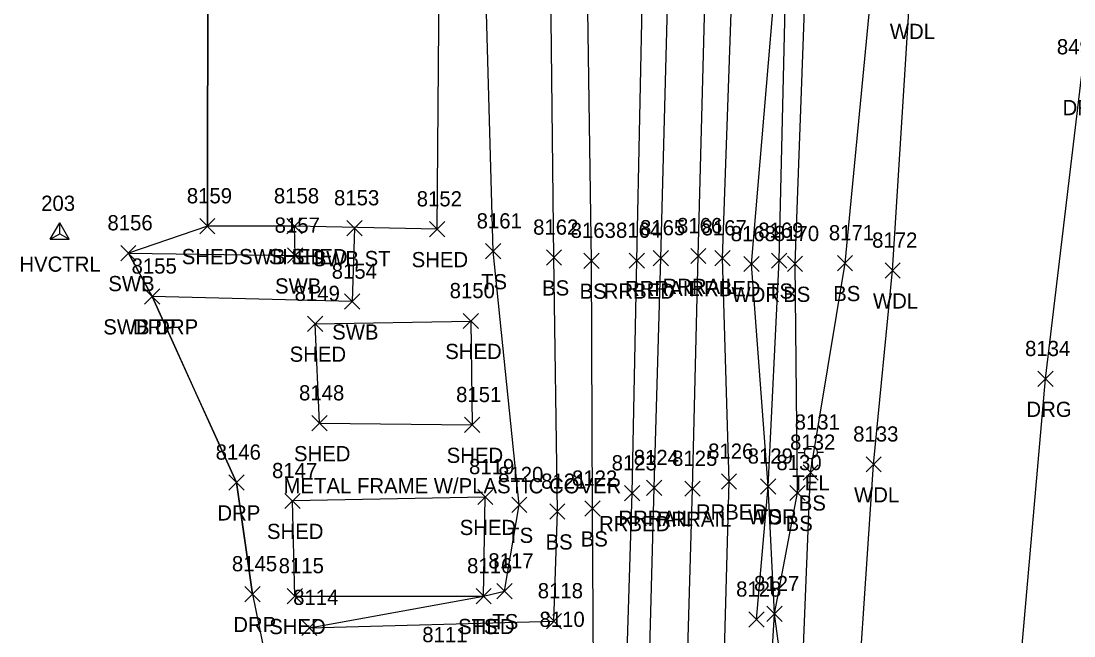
# Model space of a CAD drawing. Extents: x 1769141 to 1770911, y 735471 to 741449.
# Drawn here: x 1770186.3 to 1770324.8, y 736785 to 736865.8 of the extents above; entities that cross this region are included whole.
import ezdxf

# ---------------------------------------------------------------- set-up
doc = ezdxf.new("R2010")
doc.units = 0
for name, color, linetype in [('C_A', 7, 'Continuous'), ('C_I', 7, 'Continuous'), ('CPSM', 7, 'Continuous'), ('L_A', 7, 'Continuous'), ('L_C', 7, 'Continuous'), ('L_I', 7, 'Continuous'), ('L_TIC', 7, 'Continuous'), ('LAWA', 7, 'Continuous'), ('LBC', 7, 'Continuous'), ('LELB', 7, 'Continuous'), ('LSOGP', 7, 'Continuous'), ('R_A', 7, 'Continuous'), ('R_I', 7, 'Continuous'), ('R_TIC', 7, 'Continuous'), ('RDG', 7, 'Continuous'), ('RDP', 7, 'Continuous'), ('RR', 7, 'Continuous'), ('RRB', 7, 'Continuous'), ('RSW', 7, 'Continuous'), ('U_A', 7, 'Continuous'), ('U_I', 7, 'Continuous'), ('UP', 7, 'Continuous')]:
    doc.layers.add(name, color=color, linetype=linetype)

msp = doc.modelspace()

# ---------------------------------------------------------------- linework, layer by layer
at = {"layer": 'CPSM'}
for p, q in [((1770190.13, 736837.13), (1770191.38, 736839.3)), ((1770192.63, 736837.13), (1770191.38, 736839.3)), ((1770191.38, 736837.86), (1770191.38, 736839.3)), ((1770190.13, 736837.13), (1770191.38, 736837.86)), ((1770191.38, 736837.86), (1770191.38, 736837.86)), ((1770191.38, 736837.86), (1770192.63, 736837.13)), ((1770190.13, 736837.13), (1770192.63, 736837.13))]:
    msp.add_line(p, q, dxfattribs=at)
at = {"layer": 'L_TIC'}
for points in [[(1770209.8, 736837.85), (1770211.8, 736839.85)], [(1770211.8, 736837.85), (1770209.8, 736839.85)], [(1770221.25, 736837.85), (1770223.25, 736839.85)], [(1770223.25, 736837.85), (1770221.25, 736839.85)], [(1770240.03, 736837.45), (1770242.03, 736839.45)], [(1770242.03, 736837.45), (1770240.03, 736839.45)], [(1770240.03, 736837.45), (1770242.03, 736839.45)], [(1770242.03, 736837.45), (1770240.03, 736839.45)], [(1770247.39, 736834.55), (1770249.39, 736836.55)], [(1770249.39, 736834.55), (1770247.39, 736836.55)], [(1770255.39, 736833.73), (1770257.39, 736835.73)], [(1770257.39, 736833.73), (1770255.39, 736835.73)], [(1770260.32, 736833.3), (1770262.32, 736835.3)], [(1770262.32, 736833.3), (1770260.32, 736835.3)], [(1770281.38, 736832.87), (1770283.38, 736834.87)], [(1770283.38, 736832.87), (1770281.38, 736834.87)], [(1770285.01, 736833.32), (1770287.01, 736835.32)], [(1770287.01, 736833.32), (1770285.01, 736835.32)], [(1770287.1, 736832.89), (1770289.1, 736834.89)], [(1770289.1, 736832.89), (1770287.1, 736834.89)], [(1770293.68, 736832.99), (1770295.68, 736834.99)], [(1770295.68, 736832.99), (1770293.68, 736834.99)], [(1770299.94, 736832.02), (1770301.94, 736834.02)], [(1770301.94, 736832.02), (1770299.94, 736834.02)], [(1770223.98, 736825.02), (1770225.98, 736827.02)], [(1770225.98, 736825.02), (1770223.98, 736827.02)], [(1770244.45, 736825.38), (1770246.45, 736827.38)], [(1770246.45, 736825.38), (1770244.45, 736827.38)], [(1770224.55, 736811.94), (1770226.55, 736813.94)], [(1770226.55, 736811.94), (1770224.55, 736813.94)], [(1770224.55, 736811.94), (1770226.55, 736813.94)], [(1770226.55, 736811.94), (1770224.55, 736813.94)], [(1770244.64, 736811.72), (1770246.64, 736813.72)], [(1770246.64, 736811.72), (1770244.64, 736813.72)], [(1770244.64, 736811.72), (1770246.64, 736813.72)], [(1770246.64, 736811.72), (1770244.64, 736813.72)], [(1770297.44, 736806.53), (1770299.44, 736808.53)], [(1770299.44, 736806.53), (1770297.44, 736808.53)], [(1770289.15, 736805.45), (1770291.15, 736807.45)], [(1770291.15, 736805.45), (1770289.15, 736807.45)], [(1770289.15, 736805.45), (1770291.15, 736807.45)], [(1770291.15, 736805.45), (1770289.15, 736807.45)], [(1770283.57, 736803.63), (1770285.57, 736805.63)], [(1770285.57, 736803.63), (1770283.57, 736805.63)], [(1770283.57, 736803.63), (1770285.57, 736805.63)], [(1770285.57, 736803.63), (1770283.57, 736805.63)], [(1770246.36, 736802.24), (1770248.36, 736804.24)], [(1770248.36, 736802.24), (1770246.36, 736804.24)], [(1770287.42, 736802.77), (1770289.42, 736804.77)], [(1770289.42, 736802.77), (1770287.42, 736804.77)], [(1770221, 736801.72), (1770223, 736803.72)], [(1770223, 736801.72), (1770221, 736803.72)], [(1770221, 736801.72), (1770223, 736803.72)], [(1770223, 736801.72), (1770221, 736803.72)], [(1770250.83, 736801.2), (1770252.83, 736803.2)], [(1770252.83, 736801.2), (1770250.83, 736803.2)], [(1770260.47, 736800.73), (1770262.47, 736802.73)], [(1770262.47, 736800.73), (1770260.47, 736802.73)], [(1770255.84, 736800.33), (1770257.84, 736802.33)], [(1770257.84, 736800.33), (1770255.84, 736802.33)], [(1770248.88, 736789.85), (1770250.88, 736791.85)], [(1770250.88, 736789.85), (1770248.88, 736791.85)], [(1770221.31, 736789.21), (1770223.31, 736791.21)], [(1770223.31, 736789.21), (1770221.31, 736791.21)], [(1770221.31, 736789.21), (1770223.31, 736791.21)], [(1770223.31, 736789.21), (1770221.31, 736791.21)], [(1770246.14, 736789.21), (1770248.14, 736791.21)], [(1770248.14, 736789.21), (1770246.14, 736791.21)], [(1770246.14, 736789.21), (1770248.14, 736791.21)], [(1770248.14, 736789.21), (1770246.14, 736791.21)], [(1770284.4, 736786.87), (1770286.4, 736788.87)], [(1770286.4, 736786.87), (1770284.4, 736788.87)], [(1770284.4, 736786.87), (1770286.4, 736788.87)], [(1770286.4, 736786.87), (1770284.4, 736788.87)], [(1770255.39, 736785.92), (1770257.39, 736787.92)], [(1770257.39, 736785.92), (1770255.39, 736787.92)], [(1770282.04, 736786.14), (1770284.04, 736788.14)], [(1770284.04, 736786.14), (1770282.04, 736788.14)], [(1770223.22, 736785.05), (1770225.22, 736787.05)], [(1770225.22, 736785.05), (1770223.22, 736787.05)], [(1770223.22, 736785.05), (1770225.22, 736787.05)], [(1770225.22, 736785.05), (1770223.22, 736787.05)]]:
    msp.add_lwpolyline(points, dxfattribs=at)
at = {"layer": 'LAWA'}
for points in [[(1770295.56, 736765.07), (1770288.47, 736765.03), (1770285.4, 736787.87), (1770284.57, 736804.63), (1770282.38, 736833.87), (1770287.4, 736893.59), (1770286.58, 736936.63), (1770289.46, 736968.99), (1770291.49, 736986.73), (1770290, 737012.94), (1770290.58, 737048.83), (1770292.25, 737100.02), (1770294.09, 737129.48), (1770297.9, 737178.74), (1770298.45, 737224.98), (1770303.27, 737281.64), (1770303.62, 737324.77), (1770304.03, 737377.4)], [(1770295.56, 736765.07), (1770298.44, 736807.53), (1770300.94, 736833.02), (1770303.15, 736868.46), (1770304.73, 736899.95), (1770312.24, 736920.03), (1770307.96, 736948.77), (1770308.9, 736965.25), (1770306.38, 736996.36), (1770309.8, 737006.68), (1770311.39, 737048.91), (1770314.52, 737106.24), (1770314.64, 737122.83), (1770358.1, 737137.42)]]:
    msp.add_lwpolyline(points, dxfattribs=at)
at = {"layer": 'LBC'}
for points in [[(1770241.03, 736838.45), (1770222.25, 736838.85), (1770210.8, 736838.85), (1770210.86, 736875.84), (1770211.96, 736934.94), (1770241.81, 736934.81)], [(1770241.03, 736838.45), (1770241.81, 736934.81)], [(1770225.55, 736812.94), (1770224.98, 736826.02), (1770245.45, 736826.38), (1770245.64, 736812.72)], [(1770225.55, 736812.94), (1770245.64, 736812.72)], [(1770222.31, 736790.21), (1770247.14, 736790.21), (1770247.36, 736803.24), (1770222, 736802.72)], [(1770222.31, 736790.21), (1770222, 736802.72)]]:
    msp.add_lwpolyline(points, dxfattribs=at)
at = {"layer": 'LELB'}
for points in [[(1770224.22, 736786.05), (1770247.14, 736790.21), (1770249.88, 736790.85), (1770251.83, 736802.2), (1770248.39, 736835.55), (1770245.85, 736926.39), (1770250.04, 736949.23), (1770249.46, 736962.04), (1770235.3, 736982.59), (1770222.78, 736985.92)], [(1770278.54, 736722.58), (1770283.75, 736760.01), (1770285.4, 736787.87), (1770288.42, 736803.77), (1770288.1, 736833.89), (1770290.15, 736888.9), (1770292.54, 736921.49), (1770293.89, 736967.31), (1770294.41, 736976.29)], [(1770290.15, 736806.45), (1770294.68, 736833.99), (1770298.74, 736875.93), (1770299.66, 736922.72), (1770301.17, 736965.94), (1770297.99, 736975.93), (1770294.41, 736976.29)], [(1770224.22, 736786.05), (1770256.39, 736786.92), (1770256.84, 736801.33), (1770256.39, 736834.73), (1770255.46, 736917.15), (1770257.29, 736941.61)], [(1770261.5, 736721.42), (1770261.72, 736759.56), (1770261.47, 736801.73), (1770261.32, 736834.3), (1770260.25, 736909.24), (1770259.41, 736941.57), (1770257.29, 736941.61)], [(1770283.04, 736787.14), (1770284.57, 736804.63), (1770286.01, 736834.32), (1770287.4, 736893.59)], [(1770291.41, 736724.35), (1770288.47, 736765.03), (1770290.15, 736806.45)]]:
    msp.add_lwpolyline(points, dxfattribs=at)
at = {"layer": 'LSOGP'}
msp.add_lwpolyline([(1770222.78, 736985.92), (1770211.96, 736934.94), (1770210.86, 736875.84), (1770210.8, 736838.85), (1770200.41, 736835.3), (1770203.53, 736829.61), (1770206.3, 736823.49), (1770209.08, 736817.38), (1770211.86, 736811.26), (1770214.63, 736805.15), (1770215.68, 736797.81), (1770216.73, 736790.47), (1770221.43, 736767.51)], dxfattribs=at)
at = {"layer": 'R_TIC'}
for points in [[(1770221.25, 736837.85), (1770223.25, 736839.85)], [(1770223.25, 736837.85), (1770221.25, 736839.85)], [(1770229.16, 736837.59), (1770231.16, 736839.59)], [(1770231.16, 736837.59), (1770229.16, 736839.59)], [(1770199.41, 736834.3), (1770201.41, 736836.3)], [(1770201.41, 736834.3), (1770199.41, 736836.3)], [(1770221.34, 736833.99), (1770223.34, 736835.99)], [(1770223.34, 736833.99), (1770221.34, 736835.99)], [(1770266.29, 736833.32), (1770268.29, 736835.32)], [(1770268.29, 736833.32), (1770266.29, 736835.32)], [(1770269.45, 736833.65), (1770271.45, 736835.65)], [(1770271.45, 736833.65), (1770269.45, 736835.65)], [(1770274.38, 736833.93), (1770276.38, 736835.93)], [(1770276.38, 736833.93), (1770274.38, 736835.93)], [(1770277.55, 736833.64), (1770279.55, 736835.64)], [(1770279.55, 736833.64), (1770277.55, 736835.64)], [(1770202.53, 736828.61), (1770204.53, 736830.61)], [(1770204.53, 736828.61), (1770202.53, 736830.61)], [(1770202.53, 736828.61), (1770204.53, 736830.61)], [(1770204.53, 736828.61), (1770202.53, 736830.61)], [(1770228.85, 736827.94), (1770230.85, 736829.94)], [(1770230.85, 736827.94), (1770228.85, 736829.94)], [(1770320.05, 736817.77), (1770322.05, 736819.77)], [(1770322.05, 736817.77), (1770320.05, 736819.77)], [(1770320.05, 736817.77), (1770322.05, 736819.77)], [(1770322.05, 736817.77), (1770320.05, 736819.77)], [(1770213.63, 736804.15), (1770215.63, 736806.15)], [(1770215.63, 736804.15), (1770213.63, 736806.15)], [(1770278.42, 736804.27), (1770280.42, 736806.27)], [(1770280.42, 736804.27), (1770278.42, 736806.27)], [(1770265.68, 736802.74), (1770267.68, 736804.74)], [(1770267.68, 736802.74), (1770265.68, 736804.74)], [(1770268.57, 736803.44), (1770270.57, 736805.44)], [(1770270.57, 736803.44), (1770268.57, 736805.44)], [(1770273.62, 736803.33), (1770275.62, 736805.33)], [(1770275.62, 736803.33), (1770273.62, 736805.33)], [(1770215.73, 736789.47), (1770217.73, 736791.47)], [(1770217.73, 736789.47), (1770215.73, 736791.47)]]:
    msp.add_lwpolyline(points, dxfattribs=at)
at = {"layer": 'RDG'}
for points in [[(1770321.05, 736818.77), (1770325.8, 736858.44), (1770334.35, 736894.2), (1770350.3, 736909.29), (1770357.01, 736936.47)], [(1770306.26, 736740.41), (1770316.78, 736770.28), (1770321.05, 736818.77)]]:
    msp.add_lwpolyline(points, dxfattribs=at)
at = {"layer": 'RDP'}
msp.add_lwpolyline([(1770216.73, 736790.47), (1770214.63, 736805.15), (1770203.53, 736829.61)], dxfattribs=at)
at = {"layer": 'RR'}
for points in [[(1770267.4, 736722.31), (1770268.34, 736758.82), (1770269.57, 736804.44), (1770270.45, 736834.65), (1770272.42, 736909.27), (1770273.15, 736938.32), (1770274.05, 736970.76), (1770275.07, 737005.76), (1770276.22, 737052.19), (1770277.52, 737098.47), (1770278.47, 737131.31), (1770279.73, 737178.68), (1770281, 737226.57), (1770282.34, 737274.07)], [(1770272.41, 736722.1), (1770273.29, 736759.01), (1770274.62, 736804.33), (1770275.38, 736834.93), (1770277.26, 736906.22), (1770278.11, 736938.08), (1770278.9, 736969.65), (1770279.86, 737006.36), (1770281.15, 737052.02), (1770282.49, 737099.38), (1770283.42, 737130.8), (1770284.55, 737178.73), (1770285.97, 737226.12), (1770287.25, 737273.96)]]:
    msp.add_lwpolyline(points, dxfattribs=at)
at = {"layer": 'RRB'}
for points in [[(1770264.61, 736722.25), (1770265.29, 736759.21), (1770266.68, 736803.74), (1770267.29, 736834.32), (1770268.85, 736909.78), (1770270.22, 736938.92), (1770271.46, 736972.05), (1770272.55, 737004.83), (1770273.67, 737052.68), (1770274.45, 737097.79), (1770275.89, 737131.57), (1770277.22, 737178.3), (1770278.92, 737227.05), (1770280.11, 737274.21)], [(1770275.05, 736722.18), (1770278.17, 736759.08), (1770279.42, 736805.27), (1770278.55, 736834.64), (1770280.9, 736900.53), (1770282.38, 736937.77), (1770283.59, 736969.2), (1770283.11, 737006.43), (1770283.91, 737051.19), (1770285.56, 737099.3), (1770285.88, 737130.25), (1770287.46, 737178.49), (1770288.76, 737226.01), (1770290.63, 737273.86)]]:
    msp.add_lwpolyline(points, dxfattribs=at)
at = {"layer": 'RSW'}
msp.add_lwpolyline([(1770230.16, 736838.59), (1770229.85, 736828.94), (1770203.53, 736829.61), (1770200.41, 736835.3), (1770222.34, 736834.99), (1770222.25, 736838.85)], dxfattribs=at)
at = {"layer": 'UP'}
for p, q in [((1770288.52, 736809.1), (1770289.35, 736809.1)), ((1770290.18, 736809.1), (1770290.18, 736809.1)), ((1770291.85, 736809.1), (1770291.01, 736809.1)), ((1770291.01, 736809.1), (1770291.01, 736809.1)), ((1770291.85, 736809.1), (1770291.85, 736809.1))]:
    msp.add_line(p, q, dxfattribs=at)
msp.add_circle((1770290.18, 736809.1), 0.833, dxfattribs=at)

# ---------------------------------------------------------------- texts
at = {"layer": 'C_A'}
msp.add_text('HVCTRL', height=2, dxfattribs=at).set_placement((1770186.08, 736832.86))
at = {"layer": 'C_I'}
msp.add_text('203', height=2, dxfattribs=at).set_placement((1770188.94, 736840.86))
at = {"layer": 'L_A'}
for s, p in [('WDL', (1770300.57, 736863.46)), ('SHED', (1770207.43, 736833.85)), ('SHED', (1770218.88, 736833.85)), ('SHED', (1770237.67, 736833.45)), ('SHED', (1770237.67, 736833.45)), ('TS', (1770246.8, 736830.55)), ('BS', (1770254.83, 736829.73)), ('BS', (1770259.76, 736829.3)), ('WDR', (1770279.74, 736828.87)), ('TS', (1770284.42, 736829.32)), ('BS', (1770286.54, 736828.89)), ('BS', (1770293.12, 736828.99)), ('WDL', (1770298.35, 736828.02)), ('SHED', (1770221.62, 736821.02)), ('SHED', (1770242.09, 736821.38)), ('SHED', (1770222.19, 736807.94)), ('SHED', (1770222.19, 736807.94)), ('SHED', (1770242.28, 736807.72)), ('SHED', (1770242.28, 736807.72)), ('WDL', (1770295.86, 736802.53)), ('BS', (1770288.59, 736801.45)), ('BS', (1770288.59, 736801.45)), ('WDR', (1770281.93, 736799.63)), ('TS', (1770282.98, 736799.63)), ('SHED', (1770243.99, 736798.24)), ('BS', (1770286.87, 736798.77)), ('SHED', (1770218.64, 736797.72)), ('SHED', (1770218.64, 736797.72)), ('TS', (1770250.24, 736797.2)), ('BS', (1770259.91, 736796.73)), ('BS', (1770255.28, 736796.33)), ('TS', (1770248.29, 736785.85)), ('SHED', (1770218.94, 736785.21)), ('SHED', (1770218.94, 736785.21)), ('SHED', (1770243.78, 736785.21)), ('TS', (1770245.55, 736785.21))]:
    msp.add_text(s, height=2, dxfattribs=at).set_placement(p)
at = {"layer": 'L_C'}
msp.add_text('METAL FRAME W/PLASTIC COVER', height=2, dxfattribs=at).set_placement((1770220.82, 736803.72))
msp.add_text('METAL FRAME W/PLASTIC COVER', height=2, dxfattribs=at).set_placement((1770220.82, 736803.72))
at = {"layer": 'L_I'}
for s, p in [('8159', (1770208.1, 736841.85)), ('8158', (1770219.55, 736841.85)), ('8152', (1770238.34, 736841.45)), ('8152', (1770238.34, 736841.45)), ('8161', (1770246.22, 736838.55)), ('8162', (1770253.65, 736837.73)), ('8163', (1770258.58, 736837.3)), ('8168', (1770279.64, 736836.87)), ('8169', (1770283.26, 736837.32)), ('8170', (1770285.32, 736836.89)), ('8171', (1770292.55, 736836.99)), ('8172', (1770298.24, 736836.02)), ('8149', (1770222.28, 736829.02)), ('8150', (1770242.67, 736829.38)), ('8148', (1770222.86, 736815.94)), ('8148', (1770222.86, 736815.94)), ('8151', (1770243.52, 736815.72)), ('8151', (1770243.52, 736815.72)), ('8133', (1770295.75, 736810.53)), ('8132', (1770287.45, 736809.45)), ('8132', (1770287.45, 736809.45)), ('8129', (1770281.87, 736807.63)), ('8129', (1770281.87, 736807.63)), ('8119', (1770245.22, 736806.24)), ('8130', (1770285.65, 736806.77)), ('8147', (1770219.31, 736805.72)), ('8147', (1770219.31, 736805.72)), ('8120', (1770249.05, 736805.2)), ('8121', (1770254.71, 736804.33)), ('8122', (1770258.77, 736804.73)), ('8117', (1770247.76, 736793.85)), ('8115', (1770220.18, 736793.21)), ('8115', (1770220.18, 736793.21)), ('8116', (1770244.96, 736793.21)), ('8116', (1770244.96, 736793.21)), ('8118', (1770254.26, 736789.92)), ('8128', (1770280.35, 736790.14)), ('8127', (1770282.71, 736790.87)), ('8127', (1770282.71, 736790.87)), ('8114', (1770222.09, 736789.05)), ('8114', (1770222.09, 736789.05)), ('8110', (1770254.49, 736786.16)), ('8111', (1770239.07, 736784.15))]:
    msp.add_text(s, height=2, dxfattribs=at).set_placement(p)
at = {"layer": 'R_A'}
for s, p in [('DRG', (1770323.29, 736853.44)), ('SWB SHED', (1770214.98, 736833.85)), ('SWB ST', (1770224.65, 736833.59)), ('SWB', (1770197.77, 736830.3)), ('SWB', (1770219.7, 736829.99)), ('RRRAIL', (1770270.67, 736829.93)), ('RRBED', (1770262.94, 736829.32)), ('RRRAIL', (1770265.75, 736829.65)), ('RRBED', (1770274.2, 736829.64)), ('SWB DRP', (1770197.11, 736824.61)), ('DRP', (1770201.01, 736824.61)), ('SWB', (1770227.22, 736823.94)), ('DRG', (1770318.54, 736813.77)), ('DRG', (1770318.54, 736813.77)), ('DRP', (1770212.12, 736800.15)), ('RRRAIL', (1770264.86, 736799.44)), ('RRRAIL', (1770269.91, 736799.33)), ('RRBED', (1770275.06, 736800.27)), ('RRBED', (1770262.32, 736798.74)), ('DRP', (1770214.21, 736785.47))]:
    msp.add_text(s, height=2, dxfattribs=at).set_placement(p)
at = {"layer": 'R_I'}
for s, p in [('8498', (1770322.54, 736861.44)), ('8158', (1770219.55, 736841.85)), ('8153', (1770227.46, 736841.59)), ('8156', (1770197.66, 736838.3)), ('8157', (1770219.65, 736837.99)), ('8164', (1770264.55, 736837.32)), ('8165', (1770267.71, 736837.65)), ('8166', (1770272.58, 736837.93)), ('8167', (1770275.81, 736837.64)), ('8155', (1770200.83, 736832.61)), ('8155', (1770200.83, 736832.61)), ('8154', (1770227.16, 736831.94)), ('8134', (1770318.36, 736821.77)), ('8134', (1770318.36, 736821.77)), ('8146', (1770211.89, 736808.15)), ('8126', (1770276.67, 736808.27)), ('8123', (1770263.98, 736806.74)), ('8124', (1770266.88, 736807.44)), ('8125', (1770271.93, 736807.33)), ('8145', (1770214.03, 736793.47))]:
    msp.add_text(s, height=2, dxfattribs=at).set_placement(p)
at = {"layer": 'U_A'}
msp.add_text('TEL', height=2, dxfattribs=at).set_placement((1770287.74, 736804.1))
at = {"layer": 'U_I'}
msp.add_text('8131', height=2, dxfattribs=at).set_placement((1770288.05, 736812.1))

doc.saveas('drawing.dxf')
